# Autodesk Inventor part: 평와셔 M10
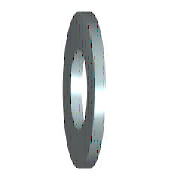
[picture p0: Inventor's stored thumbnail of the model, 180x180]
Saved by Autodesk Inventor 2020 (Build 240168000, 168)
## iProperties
Created: 2012-02
Part Number: 평와셔 M10
Material: 스테인리스강
Description: 평면 와셔 - 일반 시리즈 - 제품 등급 A
Document SubType Name: Modeling
Standard: ISO 7089
Designer: mdu-01
Standard Revision: Second edition 2000-06-01
Standards Organization: ISO
Language: ko-KR
Size Designation: 10 - 140 HV
Categories: <MemberInstance><Categories><Category DisplayName="조임쇠" InternalName="e4da775c-781d-43d5-af7c-5136215cf5a6" Mnemonic="FSTN"><Category DisplayName="와셔" InternalN
Density: 8.08 g/cm^3
Appearance: 반광택
IsCustomPart: 1
Author: mdu-01
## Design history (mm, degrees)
sketch "스케치"
  geometry: C1 r 10 at (0, 0); C2 r 5.25 at (0, 0); 1 further point
  constraints: 2 centre point, 2 coincident
  dimensions: "d0" = 10.5 diameter of C2 (= SD1); "d1" = 20 diameter of C1 (= SD2)
extrude "본체" new body sketch "스케치" distance "d2" = 2 (= SD); taper "d3" = 0 deg
workaxis "Work Axis1"
workplane "Work Plane1"
body "Solid1"
other parameters: "SD1" = 10.5 [user parameter; used in 1 equation term], "SD2" = 20 [user parameter; used in 1 equation term], "SD" = 2 [user parameter; used in 1 equation term], "d4" = 0, "d5" = 0, "d6" = 0, "d7" = 0
